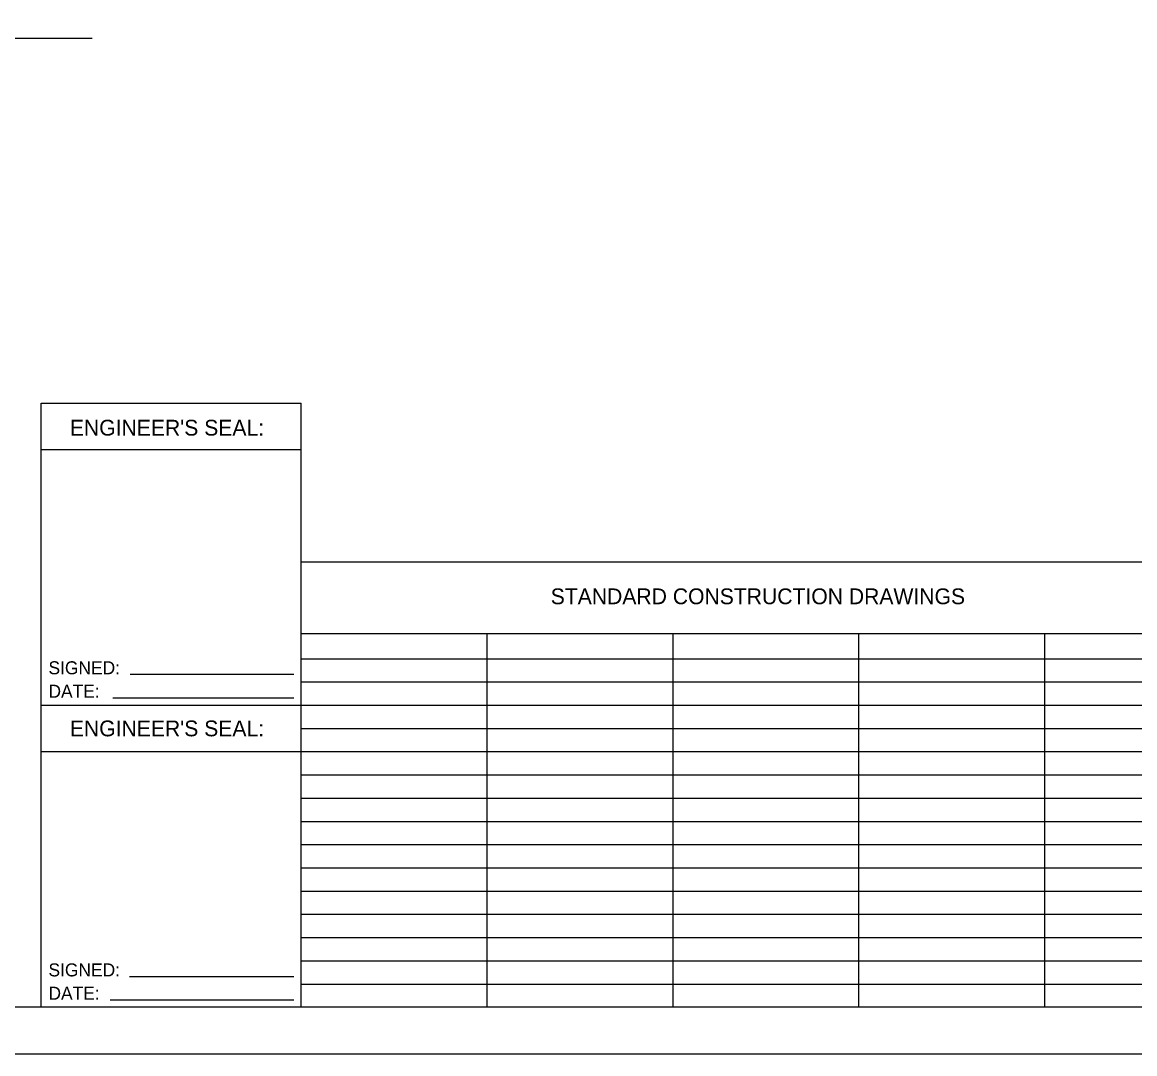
# Model space of a CAD drawing. Extents: x 0 to 34, y 0 to 22.
# Drawn here: x 8.25 to 20.22, y 0 to 11.1 of the extents above; entities that cross this region are included whole.
import ezdxf

# ---------------------------------------------------------------- set-up
doc = ezdxf.new("R2010")
doc.units = 0
for name, color, linetype in [('SH_Border', 7, 'Continuous'), ('SH_Cut_Line', 7, 'Continuous'), ('SH_Data', 7, 'Continuous'), ('SH_Text', 7, 'Continuous')]:
    doc.layers.add(name, color=color, linetype=linetype)

msp = doc.modelspace()

# ---------------------------------------------------------------- linework, layer by layer
at = {"layer": 'SH_Border'}
msp.add_lwpolyline([(1.5, 21.5), (33.5, 21.5), (33.5, 0.5), (1.5, 0.5)], close=True, dxfattribs=at)
at = {"layer": 'SH_Cut_Line'}
msp.add_lwpolyline([(0, 0), (34, 0), (34, 22), (0, 22)], close=True, dxfattribs=at)
at = {"layer": 'SH_Data'}
for p, q in [((9, 10.922), (7.75, 10.922)), ((8.45, 3.75), (8.45, 7)), ((8.45, 7), (11.25, 7)), ((11.25, 0.5), (11.25, 7)), ((8.45, 6.5), (11.25, 6.5)), ((11.25, 5.292), (24.7, 5.292)), ((11.25, 4.521), (24.7, 4.521)), ((13.25, 0.5), (13.25, 4.521)), ((15.25, 0.5), (15.25, 4.521)), ((17.25, 0.5), (17.25, 4.521)), ((19.25, 0.5), (19.25, 4.521)), ((11.25, 4.25), (24.7, 4.25)), ((11.25, 4), (24.7, 4)), ((8.45, 0.5), (8.45, 3.75)), ((8.45, 3.75), (11.25, 3.75)), ((11.25, 3.75), (24.7, 3.75)), ((11.25, 3.5), (24.7, 3.5)), ((8.45, 3.25), (11.25, 3.25)), ((11.25, 3.25), (24.7, 3.25)), ((11.25, 3), (24.7, 3)), ((11.25, 2.75), (24.7, 2.75)), ((11.25, 2.5), (24.7, 2.5)), ((11.25, 2.25), (24.7, 2.25)), ((11.25, 2), (24.7, 2)), ((11.25, 1.75), (24.7, 1.75)), ((11.25, 1.5), (24.7, 1.5)), ((11.25, 1.25), (24.7, 1.25)), ((11.25, 1), (24.7, 1)), ((11.25, 0.75), (24.7, 0.75))]:
    msp.add_line(p, q, dxfattribs=at)
at = {"layer": 'SH_Text'}
for p, q in [((9.408, 4.082), (11.171, 4.082)), ((9.222, 3.83), (11.171, 3.83)), ((9.401, 0.832), (11.171, 0.832)), ((9.193, 0.581), (11.171, 0.581))]:
    msp.add_line(p, q, dxfattribs=at)

# ---------------------------------------------------------------- texts
for s, height, p in [("ENGINEER'S SEAL:", 0.17, (8.76, 6.65)), ('STANDARD CONSTRUCTION DRAWINGS', 0.17, (13.934, 4.836)), ('SIGNED:', 0.14, (8.53, 4.082)), ('DATE:', 0.14, (8.53, 3.83)), ("ENGINEER'S SEAL:", 0.17, (8.76, 3.415)), ('SIGNED:', 0.14, (8.53, 0.832)), ('DATE:', 0.14, (8.53, 0.581))]:
    msp.add_text(s, height=height, dxfattribs=at).set_placement(p)

doc.saveas('drawing.dxf')
